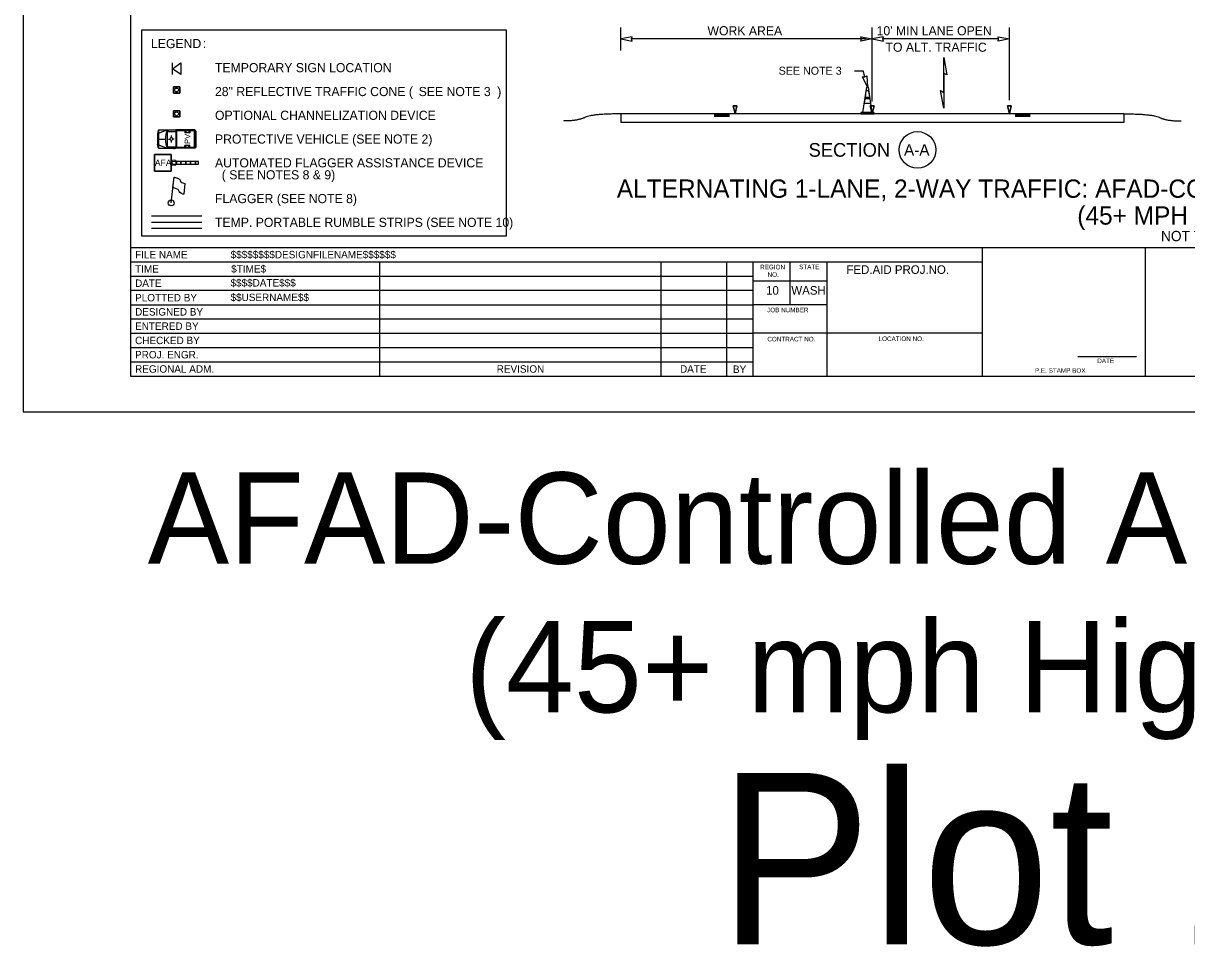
# Model space of a CAD drawing. Extents: x 99999.1 to 100095.7, y 99995 to 100010.7.
# Drawn here: x 99999.06 to 100009.24, y 99995.01 to 100003.09 of the extents above; entities that cross this region are included whole.
import ezdxf

# ---------------------------------------------------------------- set-up
doc = ezdxf.new("R2010")
doc.units = 0
for name, color, linetype in [('SH_DE_DetailHeading1Text', 7, 'Continuous'), ('SH_GI_PlotLimits', 7, 'Continuous'), ('SH_GI_SheetBorder', 7, 'Continuous'), ('SH_GI_SheetLocationText', 7, 'Continuous'), ('SH_GI_SheetTextInCells', 7, 'Continuous'), ('SH_GI_TitleBlockText', 7, 'Continuous'), ('TR_WZ_AFAD', 7, 'Continuous'), ('TR_WZ_FlaggingStation', 7, 'Continuous'), ('TR_WZ_PortableSignMountBlk-Org', 7, 'Continuous'), ('TR_WZ_ProtectiveVehicle', 7, 'Continuous'), ('TR_WZ_TrafficCone', 7, 'Continuous'), ('TR_WZ_TrafficConeElev', 7, 'Continuous'), ('TR_WZ_WorkZoneDetails', 7, 'Continuous'), ('TR_WZ_WorkZoneTextCurrent', 7, 'Continuous')]:
    doc.layers.add(name, color=color, linetype=linetype)

msp = doc.modelspace()

# ---------------------------------------------------------------- linework, layer by layer
at = {"layer": 'SH_GI_PlotLimits'}
msp.add_lwpolyline([(99999.062, 99999.687), (100016.062, 99999.687), (100016.062, 100010.687), (99999.062, 100010.687)], close=True, dxfattribs=at)
at = {"layer": 'SH_GI_SheetBorder'}
for p, q in [((100000, 100010.375), (100000, 100000)), ((100000, 100001.126), (100015.75, 100001.126)), ((100007.457, 100000), (100007.457, 100001.126)), ((100008.883, 100000), (100008.883, 100001.126)), ((100000, 100001.001), (100007.457, 100001.001)), ((100002.179, 100001.001), (100002.179, 100000)), ((100004.641, 100001.001), (100004.641, 100000)), ((100005.216, 100001.001), (100005.216, 100000)), ((100005.445, 100001.001), (100005.445, 100000)), ((100005.772, 100000.625), (100005.772, 100001.001)), ((100006.096, 100000), (100006.096, 100001.001)), ((100000, 100000.876), (100002.182, 100000.876)), ((100002.182, 100000.876), (100005.447, 100000.876)), ((100006.096, 100000.831), (100005.447, 100000.831)), ((100000, 100000.751), (100002.182, 100000.751)), ((100002.182, 100000.751), (100005.447, 100000.751)), ((100000, 100000.625), (100005.447, 100000.625)), ((100006.096, 100000.625), (100005.447, 100000.625)), ((100000, 100000.5), (100005.447, 100000.5)), ((100000, 100000.375), (100005.447, 100000.375)), ((100007.457, 100000.375), (100005.447, 100000.375)), ((100000, 100000.25), (100005.447, 100000.25)), ((100000, 100000.125), (100005.447, 100000.125)), ((100008.29, 100000.173), (100008.802, 100000.173)), ((100000, 100000), (100015.75, 100000))]:
    msp.add_line(p, q, dxfattribs=at)
at = {"layer": 'TR_WZ_AFAD'}
for p, q in [((100000.212, 100001.795), (100000.212, 100001.939)), ((100000.212, 100001.939), (100000.356, 100001.939)), ((100000.356, 100001.939), (100000.212, 100001.939)), ((100000.212, 100001.939), (100000.212, 100001.795)), ((100000.356, 100001.939), (100000.356, 100001.795)), ((100000.356, 100001.872), (100000.356, 100001.939)), ((100000.399, 100001.879), (100000.356, 100001.879)), ((100000.356, 100001.879), (100000.356, 100001.872)), ((100000.356, 100001.872), (100000.356, 100001.867)), ((100000.441, 100001.879), (100000.399, 100001.879)), ((100000.399, 100001.855), (100000.441, 100001.855)), ((100000.484, 100001.879), (100000.441, 100001.879)), ((100000.441, 100001.867), (100000.441, 100001.879)), ((100000.441, 100001.855), (100000.441, 100001.867)), ((100000.441, 100001.855), (100000.484, 100001.855)), ((100000.527, 100001.879), (100000.484, 100001.879)), ((100000.484, 100001.879), (100000.484, 100001.867)), ((100000.484, 100001.867), (100000.484, 100001.855)), ((100000.484, 100001.855), (100000.527, 100001.855)), ((100000.569, 100001.879), (100000.527, 100001.879)), ((100000.527, 100001.867), (100000.527, 100001.879)), ((100000.527, 100001.855), (100000.527, 100001.867)), ((100000.527, 100001.855), (100000.569, 100001.855)), ((100000.569, 100001.879), (100000.569, 100001.867)), ((100000.569, 100001.867), (100000.569, 100001.855)), ((100000.569, 100001.855), (100000.596, 100001.855)), ((100000.356, 100001.795), (100000.212, 100001.795)), ((100000.212, 100001.795), (100000.356, 100001.795))]:
    msp.add_line(p, q, dxfattribs=at)
for points in [[(100000.356, 100001.855), (100000.596, 100001.855), (100000.596, 100001.879), (100000.356, 100001.879)], [(100000.356, 100001.795), (100000.356, 100001.861), (100000.356, 100001.872)], [(100000.356, 100001.867), (100000.356, 100001.861), (100000.356, 100001.855), (100000.399, 100001.855)], [(100000.399, 100001.855), (100000.399, 100001.867), (100000.399, 100001.879)], [(100000.399, 100001.879), (100000.399, 100001.867), (100000.399, 100001.855)], [(100000.441, 100001.879), (100000.441, 100001.867), (100000.441, 100001.855)], [(100000.484, 100001.855), (100000.484, 100001.867), (100000.484, 100001.879)], [(100000.527, 100001.879), (100000.527, 100001.867), (100000.527, 100001.855)], [(100000.569, 100001.855), (100000.569, 100001.867), (100000.569, 100001.879)], [(100000.596, 100001.855), (100000.596, 100001.879), (100000.569, 100001.879)]]:
    msp.add_lwpolyline(points, dxfattribs=at)
at = {"layer": 'TR_WZ_FlaggingStation'}
for p, q in [((100000.357, 100001.516), (100000.383, 100001.741)), ((100000.372, 100001.65), (100000.383, 100001.741)), ((100000.372, 100001.65), (100000.372, 100001.65)), ((100000.477, 100001.687), (100000.467, 100001.593))]:
    msp.add_line(p, q, dxfattribs=at)
for points in [[(100000.383, 100001.741), (100000.387, 100001.74), (100000.402, 100001.737), (100000.413, 100001.734), (100000.42, 100001.729), (100000.427, 100001.725), (100000.432, 100001.72), (100000.435, 100001.714), (100000.436, 100001.709), (100000.44, 100001.701), (100000.449, 100001.695), (100000.458, 100001.691), (100000.477, 100001.687)], [(100000.467, 100001.593), (100000.46, 100001.594), (100000.446, 100001.598), (100000.433, 100001.606), (100000.428, 100001.615), (100000.425, 100001.623), (100000.418, 100001.632), (100000.409, 100001.637), (100000.395, 100001.642), (100000.372, 100001.65)]]:
    msp.add_lwpolyline(points, dxfattribs=at)
msp.add_circle((100000.357, 100001.516), 0.026, dxfattribs=at)
at = {"layer": 'TR_WZ_PortableSignMountBlk-Org'}
msp.add_line((100000.368, 100002.641), (100000.368, 100002.741), dxfattribs=at)
msp.add_lwpolyline([(100000.368, 100002.691), (100000.44, 100002.741), (100000.44, 100002.641)], close=True, dxfattribs=at)
at = {"layer": 'TR_WZ_ProtectiveVehicle'}
for p, q in [((100000.245, 100002.155), (100000.238, 100002.123)), ((100000.245, 100002.155), (100000.245, 100001.995)), ((100000.245, 100002.155), (100000.396, 100002.155)), ((100000.245, 100002.126), (100000.321, 100002.155)), ((100000.321, 100002.155), (100000.321, 100001.995)), ((100000.322, 100002.155), (100000.322, 100001.995)), ((100000.322, 100002.155), (100000.332, 100002.142)), ((100000.322, 100002.142), (100000.396, 100002.142)), ((100000.376, 100002.157), (100000.385, 100002.157)), ((100000.396, 100002.155), (100000.396, 100001.995)), ((100000.563, 100002.155), (100000.398, 100002.155)), ((100000.398, 100002.155), (100000.398, 100001.995)), ((100000.558, 100002.148), (100000.403, 100002.148)), ((100000.403, 100002.148), (100000.403, 100002.001)), ((100000.477, 100002.148), (100000.477, 100002.13)), ((100000.485, 100002.148), (100000.485, 100002.13)), ((100000.512, 100002.148), (100000.512, 100002.13)), ((100000.521, 100002.148), (100000.521, 100002.13)), ((100000.558, 100002.148), (100000.558, 100002.001)), ((100000.563, 100002.155), (100000.563, 100001.995)), ((100000.567, 100002.152), (100000.563, 100002.152)), ((100000.563, 100002.152), (100000.563, 100001.998)), ((100000.571, 100002.147), (100000.571, 100002.002)), ((100000.238, 100002.123), (100000.238, 100002.027)), ((100000.245, 100002.075), (100000.306, 100002.075)), ((100000.334, 100002.075), (100000.344, 100002.075)), ((100000.358, 100002.107), (100000.358, 100002.094)), ((100000.359, 100002.044), (100000.359, 100002.056)), ((100000.37, 100002.075), (100000.37, 100002.075)), ((100000.383, 100002.074), (100000.371, 100002.075)), ((100000.521, 100002.13), (100000.477, 100002.13)), ((100000.571, 100002.086), (100000.563, 100002.083)), ((100000.571, 100002.064), (100000.563, 100002.067)), ((100000.569, 100002.075), (100000.565, 100002.075)), ((100000.567, 100002.077), (100000.567, 100002.073)), ((100000.245, 100001.995), (100000.238, 100002.027)), ((100000.245, 100002.024), (100000.321, 100001.995)), ((100000.245, 100001.995), (100000.396, 100001.995)), ((100000.322, 100002.007), (100000.396, 100002.007)), ((100000.33, 100002.007), (100000.322, 100001.995)), ((100000.376, 100001.993), (100000.385, 100001.993)), ((100000.563, 100001.995), (100000.398, 100001.995)), ((100000.558, 100002.001), (100000.403, 100002.001)), ((100000.477, 100002.001), (100000.477, 100002.02)), ((100000.521, 100002.02), (100000.477, 100002.02)), ((100000.485, 100002.001), (100000.485, 100002.02)), ((100000.512, 100002.001), (100000.512, 100002.02)), ((100000.521, 100002.001), (100000.521, 100002.02)), ((100000.567, 100001.998), (100000.563, 100001.998))]:
    msp.add_line(p, q, dxfattribs=at)
for centre, major_axis, start_param, end_param in [((100000.429, 100002.075), (0, -0.168), 4.215667, 5.208926), ((100000.567, 100002.147), (0, 0.00488), 4.712389, 6.283185), ((100000.567, 100002.002), (0, -0.00488), 0, 1.570796)]:
    msp.add_ellipse(centre, major_axis=major_axis, ratio=0.73155, start_param=start_param, end_param=end_param, dxfattribs=at)
for centre, major_axis in [((100000.358, 100002.075), (0, 0.0154)), ((100000.567, 100002.075), (0, 0.00225))]:
    msp.add_ellipse(centre, major_axis=major_axis, ratio=0.73155, dxfattribs=at)
at = {"layer": 'TR_WZ_TrafficCone'}
for points in [[(100000.377, 100002.531), (100000.431, 100002.531), (100000.431, 100002.478), (100000.377, 100002.478), (100000.377, 100002.531)], [(100000.377, 100002.478), (100000.431, 100002.478), (100000.431, 100002.531), (100000.377, 100002.531), (100000.377, 100002.478)], [(100000.377, 100002.323), (100000.431, 100002.323), (100000.431, 100002.27), (100000.377, 100002.27), (100000.377, 100002.323)], [(100000.377, 100002.27), (100000.431, 100002.27), (100000.431, 100002.323), (100000.377, 100002.323), (100000.377, 100002.27)]]:
    msp.add_lwpolyline(points, dxfattribs=at)
for centre in [(100000.404, 100002.505), (100000.404, 100002.296)]:
    msp.add_circle(centre, 0.0167, dxfattribs=at)
at = {"layer": 'TR_WZ_TrafficConeElev'}
for p, q in [((100006.436, 100002.498), (100006.428, 100002.443)), ((100006.428, 100002.443), (100006.47, 100002.443)), ((100006.462, 100002.498), (100006.436, 100002.498)), ((100006.47, 100002.443), (100006.462, 100002.498)), ((100006.425, 100002.427), (100006.42, 100002.389)), ((100006.42, 100002.389), (100006.478, 100002.389)), ((100006.472, 100002.427), (100006.425, 100002.427)), ((100006.478, 100002.389), (100006.472, 100002.427)), ((100006.395, 100002.308), (100006.391, 100002.304)), ((100006.391, 100002.304), (100006.391, 100002.296)), ((100006.391, 100002.296), (100006.507, 100002.296)), ((100006.407, 100002.308), (100006.395, 100002.308)), ((100006.507, 100002.304), (100006.503, 100002.308)), ((100006.507, 100002.296), (100006.507, 100002.304))]:
    msp.add_line(p, q, dxfattribs=at)
msp.add_lwpolyline([(100006.407, 100002.308), (100006.491, 100002.308), (100006.457, 100002.529), (100006.441, 100002.529)], close=True, dxfattribs=at)
msp.add_lwpolyline([(100006.407, 100002.308), (100006.491, 100002.308), (100006.457, 100002.529), (100006.441, 100002.529)], close=True, dxfattribs=at)
msp.add_lwpolyline([(100006.503, 100002.308), (100006.491, 100002.308), (100006.407, 100002.308)], dxfattribs=at)
at = {"layer": 'TR_WZ_WorkZoneDetails'}
for p, q in [((100004.291, 100002.851), (100004.291, 100003.051)), ((100006.491, 100002.405), (100006.491, 100003.051)), ((100007.691, 100002.415), (100007.691, 100003.051)), ((100006.439, 100002.951), (100004.384, 100002.951)), ((100007.597, 100002.951), (100006.584, 100002.951)), ((100006.336, 100002.672), (100006.412, 100002.672)), ((100006.425, 100002.62), (100006.412, 100002.672)), ((100007.116, 100002.652), (100007.116, 100002.483)), ((100007.116, 100002.483), (100007.116, 100002.652)), ((100004.291, 100002.295), (100004.291, 100002.22)), ((100008.691, 100002.295), (100004.291, 100002.295)), ((100005.108, 100002.29), (100005.241, 100002.29)), ((100005.108, 100002.285), (100005.241, 100002.285)), ((100005.108, 100002.279), (100005.241, 100002.279)), ((100005.108, 100002.274), (100005.241, 100002.274)), ((100007.874, 100002.29), (100007.741, 100002.29)), ((100007.874, 100002.284), (100007.741, 100002.284)), ((100007.874, 100002.278), (100007.741, 100002.278)), ((100007.874, 100002.273), (100007.741, 100002.273)), ((100008.691, 100002.295), (100008.691, 100002.22)), ((100008.691, 100002.22), (100004.291, 100002.22)), ((100000.624, 100001.401), (100000.184, 100001.401)), ((100000.624, 100001.346), (100000.184, 100001.346)), ((100000.624, 100001.291), (100000.184, 100001.291))]:
    msp.add_line(p, q, dxfattribs=at)
for points in [[(100004.291, 100002.951), (100004.389, 100002.932), (100004.384, 100002.951), (100004.389, 100002.971)], [(100006.491, 100002.951), (100006.392, 100002.932), (100006.397, 100002.951), (100006.392, 100002.971)], [(100006.491, 100002.951), (100006.589, 100002.932), (100006.584, 100002.951), (100006.589, 100002.971)], [(100007.691, 100002.951), (100007.592, 100002.932), (100007.597, 100002.951), (100007.592, 100002.971)], [(100007.116, 100002.789), (100007.143, 100002.636), (100007.116, 100002.652)], [(100006.449, 100002.529), (100006.406, 100002.619), (100006.426, 100002.62), (100006.443, 100002.629)], [(100007.116, 100002.345), (100007.089, 100002.499), (100007.116, 100002.483)], [(100005.291, 100002.295), (100005.274, 100002.365), (100005.307, 100002.365)], [(100006.491, 100002.295), (100006.474, 100002.365), (100006.507, 100002.365)], [(100007.691, 100002.295), (100007.674, 100002.365), (100007.707, 100002.365)]]:
    msp.add_lwpolyline(points, close=True, dxfattribs=at)
for points in [[(100005.307, 100002.365), (100005.274, 100002.365), (100005.291, 100002.295), (100005.307, 100002.365)], [(100006.507, 100002.365), (100006.474, 100002.365), (100006.491, 100002.295), (100006.507, 100002.365)], [(100007.707, 100002.365), (100007.674, 100002.365), (100007.691, 100002.295), (100007.707, 100002.365)]]:
    msp.add_lwpolyline(points, dxfattribs=at)
msp.add_circle((100006.887, 100001.98), 0.16, dxfattribs=at)
for points in [[(100004.291, 100002.295), (100004.04, 100002.295), (100003.914, 100002.233), (100003.789, 100002.233)], [(100008.691, 100002.295), (100008.942, 100002.296), (100009.067, 100002.233), (100009.193, 100002.234)]]:
    msp.add_open_spline(points, degree=2, dxfattribs=at)
at = {"layer": 'TR_WZ_WorkZoneTextCurrent'}
msp.add_lwpolyline([(100000.1, 100003.031), (100003.289, 100003.031), (100003.289, 100001.226), (100000.1, 100001.226)], close=True, dxfattribs=at)

# ---------------------------------------------------------------- texts
at = {"layer": 'SH_DE_DetailHeading1Text'}
for s, height, p in [('ALTERNATING 1-LANE, 2-WAY TRAFFIC: AFAD-CONTROLLED + TEMPORARY RUMBLE STRIPS', 0.16, (100004.256, 100001.561)), ('(45+ MPH HIGHWAYS)', 0.16, (100008.285, 100001.326)), ('NOT TO SCALE', 0.09, (100009.017, 100001.181))]:
    msp.add_text(s, height=height, rotation=360, dxfattribs=at).set_placement(p)
at = {"layer": 'SH_GI_SheetLocationText'}
for s, height, p in [('AFAD-Controlled Alt Traffic + RS', 0.8, (100000.151, 99998.357)), ('(45+ mph Highways)', 0.8, (100002.929, 99997.057)), ('Plot 1', 1.5, (100005.145, 99995.027))]:
    msp.add_text(s, height=height, dxfattribs=at).set_placement(p)
at = {"layer": 'SH_GI_SheetTextInCells'}
for s, height, p in [('FILE NAME', 0.0651, (100000.041, 100001.031)), ('TIME', 0.0651, (100000.041, 100000.906)), ('REGION', 0.04, (100005.51, 100000.935)), ('STATE', 0.04, (100005.851, 100000.936)), ('FED.AID PROJ.NO.', 0.07506, (100006.265, 100000.895)), ('DATE', 0.0651, (100000.041, 100000.781)), ('NO.', 0.04, (100005.575, 100000.869)), ('PLOTTED BY', 0.0651, (100000.041, 100000.654)), ('10', 0.0751, (100005.562, 100000.713)), ('WASH', 0.0751, (100005.783, 100000.713)), ('DESIGNED BY', 0.06505, (100000.041, 100000.53)), ('JOB NUMBER', 0.04, (100005.571, 100000.559)), ('ENTERED BY', 0.0651, (100000.041, 100000.405)), ('CHECKED BY', 0.0651, (100000.041, 100000.28)), ('CONTRACT NO.', 0.04003, (100005.573, 100000.304)), ('LOCATION NO.', 0.04003, (100006.546, 100000.307)), ('PROJ. ENGR.', 0.06505, (100000.041, 100000.155)), ('DATE', 0.04, (100008.46, 100000.114)), ('REGIONAL ADM.', 0.06505, (100000.041, 100000.03)), ('REVISION', 0.0651, (100003.205, 100000.03)), ('DATE', 0.0651, (100004.809, 100000.03)), ('BY', 0.0651, (100005.272, 100000.028)), ('P.E. STAMP BOX', 0.04003, (100007.915, 100000.029))]:
    msp.add_text(s, height=height, dxfattribs=at).set_placement(p)
at = {"layer": 'SH_GI_TitleBlockText'}
for s, height, p in [('$$$$$$$$DESIGNFILENAME$$$$$$', 0.06505, (100000.877, 100001.031)), ('$TIME$', 0.0651, (100000.882, 100000.906)), ('$$$$DATE$$$', 0.06505, (100000.876, 100000.784)), ('$$USERNAME$$', 0.06505, (100000.876, 100000.657))]:
    msp.add_text(s, height=height, dxfattribs=at).set_placement(p)
at = {"layer": 'TR_WZ_AFAD'}
msp.add_text('AFAD', height=0.056, dxfattribs=at).set_placement((100000.214, 100001.839))
at = {"layer": 'TR_WZ_ProtectiveVehicle'}
msp.add_text('PV', height=0.048, rotation=90, dxfattribs=at).set_placement((100000.523, 100002.032))
at = {"layer": 'TR_WZ_WorkZoneDetails'}
for s, p in [('WORK AREA', (100005.049, 100002.983)), ("10' MIN LANE OPEN", (100006.529, 100002.983)), ('TO ALT. TRAFFIC', (100006.607, 100002.839))]:
    msp.add_text(s, height=0.08, dxfattribs=at).set_placement(p)
for s, height, p in [('SECTION', 0.12, (100005.934, 100001.92)), ('A-A', 0.1, (100006.769, 100001.93))]:
    msp.add_text(s, height=height, rotation=360, dxfattribs=at).set_placement(p)
at = {"layer": 'TR_WZ_WorkZoneTextCurrent'}
for s, p in [('LEGEND', (100000.18, 100002.871)), (':', (100000.633, 100002.871)), ('TEMPORARY SIGN LOCATION ', (100000.74, 100002.66)), ('28" REFLECTIVE TRAFFIC CONE (', (100000.74, 100002.451)), ('SEE NOTE 3', (100002.522, 100002.451)), (')', (100003.21, 100002.451)), ('OPTIONAL CHANNELIZATION DEVICE', (100000.74, 100002.243)), ('PROTECTIVE VEHICLE (SEE NOTE 2)', (100000.74, 100002.035)), ('AUTOMATED FLAGGER ASSISTANCE DEVICE', (100000.74, 100001.827)), ('  ( SEE NOTES 8 & 9)', (100000.74, 100001.722)), ('FLAGGER (SEE NOTE 8)', (100000.74, 100001.514)), ('TEMP. PORTABLE RUMBLE STRIPS (SEE NOTE 10)', (100000.74, 100001.306))]:
    msp.add_text(s, height=0.08, rotation=360, dxfattribs=at).set_placement(p)
msp.add_text('SEE NOTE 3', height=0.07, dxfattribs=at).set_placement((100005.672, 100002.638))

doc.saveas('drawing.dxf')
